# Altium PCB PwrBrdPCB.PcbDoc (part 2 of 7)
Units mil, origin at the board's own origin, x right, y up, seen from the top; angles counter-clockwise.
Board outline 8000 x 5500 mil, 4 copper layers (Top Layer, Internal 1, Internal 2, Bottom Layer), stack 61.834 mil thick; 682 components, 380 nets, 1899 pads, 766 vias.
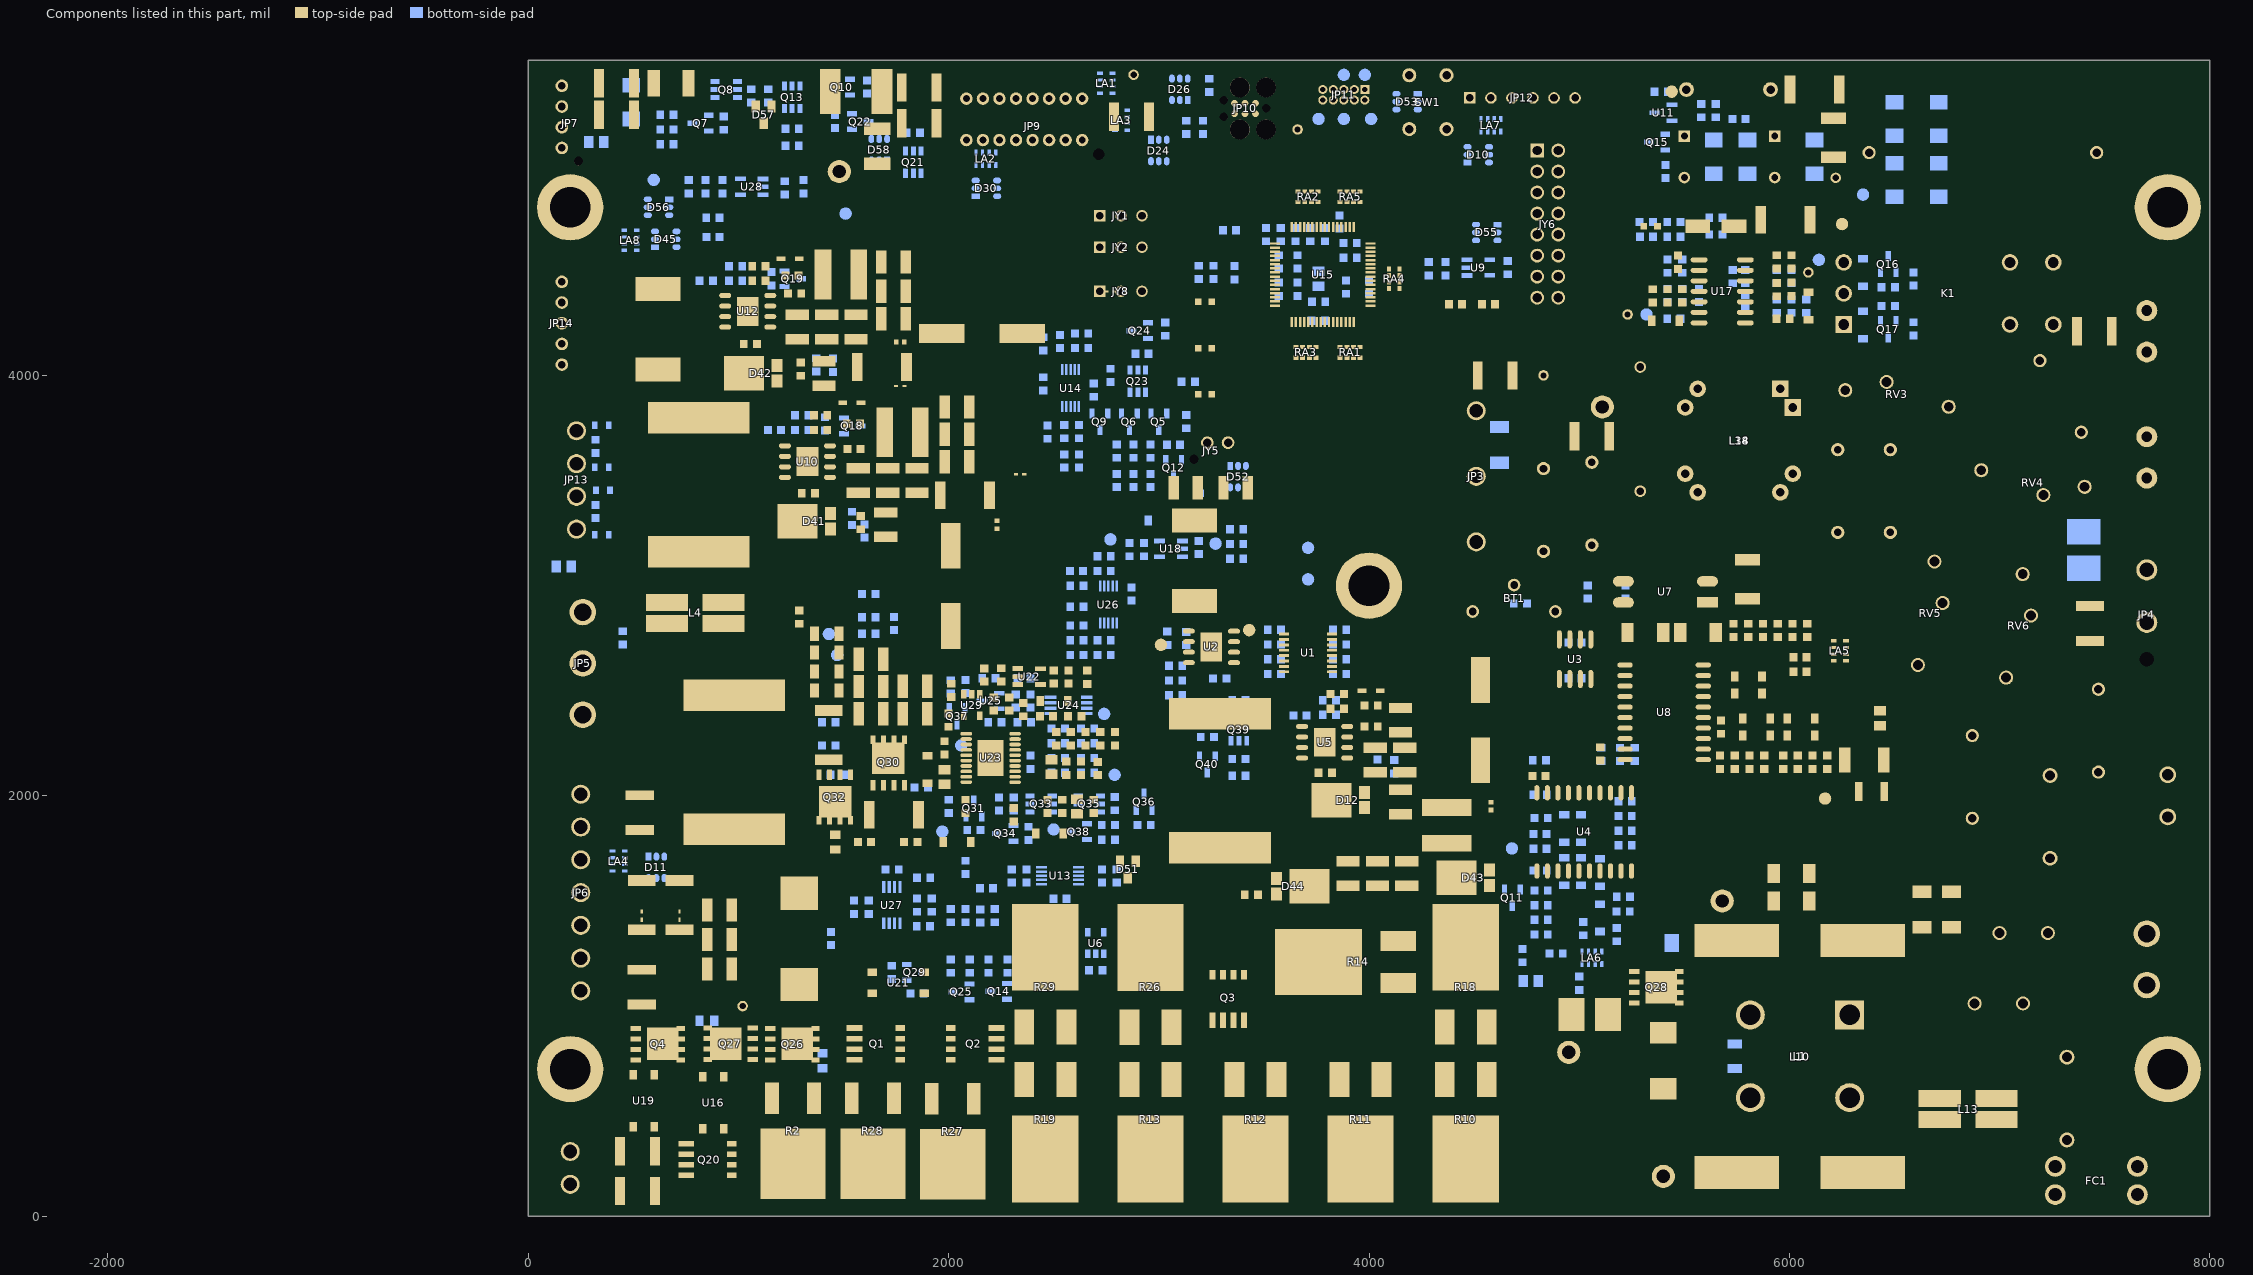
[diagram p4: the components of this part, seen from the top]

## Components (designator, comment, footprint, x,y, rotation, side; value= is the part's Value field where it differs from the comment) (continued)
R107 "1/10W 0603 0.1%" RESC1608X05AN[0603] 5580,5260 r270 bottom value=4220
R108 "1/10W 0603 0.1%" RESC1608X05AN[0603] 5650,4750 r0 bottom value=27400
R109 "1/10W 0603 1%" RESC1608X05AN[0603] 5320,4660 r180 bottom value=1000
R110 "1/10W 0603 1%" RESC1608X05AN[0603] 5450,4660 r180 bottom value=1000
R111 "1/10W 0603 1%" RESC1608X05AN[0603] 1550,3650 r180 top value=332000
R112 "1/10W 0603 1%" RESC1608X05AN[0603] 1600,3260 r90 bottom value=162000
R113 "1/10W 0603 1%" RESC1608X05AN[0603] 1171.5,3740 r0 bottom value=13000
R114 "1/10W 0603 1%" RESC1608X05AN[0603] 1547.13,3770 r0 top value=100000
R115 "1/10W 0603 1%" RESC1608X05AN[0603] 1540,3320 r90 bottom value=10000
R116 "1/10W 0603 1%" RESC1608X05AN[0603] 1391.5,3740 r180 top value=332000
R117 "1/10W 0603 1%" RESC1608X05AN[0603] 1391.5,3810 r180 top value=140000
R118 "3W 2512 1%" RESC6534X70[2512] 2077.13,3430 r180 top value=0.025
R119 "1/10W 0603 1%" RESC1608X05AN[0603] 1267.47,4390 r180 top value=332000
R120 "1/10W 0603 1%" RESC1608X05AN[0603] 1370,4050 r90 bottom value=52300
R121 "1/10W 0603 1%" RESC1608X05AN[0603] 847.13,4450 r0 bottom value=13000
R122 "1/10W 0603 1%" RESC1608X05AN[0603] 1157.13,4460 r90 bottom value=100000
R123 "1/10W 0603 1%" RESC1608X05AN[0603] 1255,4474.99 r0 top value=100000
R124 "1/10W 0603 1%" RESC1608X05AN[0603] 1450,4048.5 r90 bottom value=10000
R125 "1/10W 0603 1%" RESC1608X05AN[0603] 1097.13,4450 r180 top value=274000
R126 "1/10W 0603 1%" RESC1608X05AN[0603] 1097.13,4520 r180 top value=140000
R127 "3W 2512 1%" RESC6534X70[2512] 1682.87,4040 r180 top value=0.025
R128 "1/10W 0603 1%" RESC1608X05AN[0603] 2150,1428.5 r90 bottom value=1000
R129 "1/10W 0603 1%" RESC1608X05AN[0603] 2220,1430 r90 bottom value=1000
R130 "1/10W 0603 1%" RESC1608X05AN[0603] 2010,1430 r90 bottom value=1000
R131 "1/10W 0603 1%" RESC1608X05AN[0603] 2080,1430 r90 bottom value=1000
R132 "1/10W 0603 1%" RESC1608X05AN[0603] 2620,3592.87 r90 bottom value=1000
R133 "1/10W 0603 1%" RESC1608X05AN[0603] 2550,3592.87 r90 bottom value=1000
R134 "1/10W 0603 1%" RESC1608X05AN[0603] 2450,3960 r90 bottom value=1000
R135 "1/10W 0603 1%" RESC1608X05AN[0603] 2450,4150 r90 bottom value=1000
R136 "1/16W 0402" RESC1005X40[0402] 2230,3290 r270 top value=0.1
R137 "1/16W 0402" RESC1005X40[0402] 1770,4160 r0 top value=0.1
R138 "1/16W 0402" RESC1005X40[0402] 4580,1951.5 r90 top value=0.1
R139 "1/10W 0603 1%" RESC1608X05AN[0603] 930,5200 r270 bottom value=100000
R140 "3W 2512 1%" RESC6534X70[2512] 540,1480 r90 top value=0.01
R141 "1/10W 0603 1%" RESC1608X05AN[0603] 4411.5,4339.03 r0 top value=475000
R142 "1/10W 0603 1%" RESC1608X05AN[0603] 3380.95,2175.43 r0 bottom value=100000
R143 "1/10W 0603 1%" RESC1608X05AN[0603] 3380.95,2095.43 r0 bottom value=1000
R144 "1/10W 0603 1%" RESC1608X05AN[0603] 3232.25,2365.22 r180 bottom value=1000
R145 "1/10W 0603 1%" RESC1608X05AN[0603] 3380.95,2455.43 r0 bottom value=100000
R146 "1/10W 0603 1%" RESC1608X05AN[0603] 3230.95,2280 r180 bottom value=100000
R147 "1/10W 0603 1%" RESC1608X05AN[0603] 3360,4488.28 r90 bottom value=1000
R148 "1/10W 0603 1%" RESC1608X05AN[0603] 2465.8,2378.5 r180 top value=332000
R149 "1/10W 0603 1%" RESC1608X05AN[0603] 2355.3,2410 r90 top value=100000
R150 "1/10W 0603 1%" RESC1608X05AN[0603] 2214.78,2437.24 r90 top value=100000
R151 "1/10W 0603 1%" RESC1608X05AN[0603] 3336.5,4690.55 r180 bottom value=1000
R152 "1/10W 0603 1%" RESC1608X05AN[0603] 4568.5,4339.03 r180 top value=10000
R153 "1/10W 0603 1%" RESC1608X05AN[0603] 2190,1190 r90 bottom value=200
R154 "1/10W 0603 1%" RESC1608X05AN[0603] 2010,1190 r90 bottom value=200
R155 "1/10W 0603 1%" RESC1608X05AN[0603] 2280,1190 r270 bottom value=4750
R156 "1/10W 0603 1%" RESC1608X05AN[0603] 2100,1190 r270 bottom value=4750
R157 "1/10W 0603 1%" RESC1608X05AN[0603] 1850,1060 r180 bottom value=200
R158 "1/10W 0603 1%" RESC1608X05AN[0603] 1730,1160 r270 bottom value=4750
R159 "1/10W 0603 pulse" RESC1608X05AN[0603] 2310,1910 r90 top value=10
R160 "3W 2512 1%" RESC6534X70[2512] 720,1480 r90 top value=0.01
R161 "1/10W 0603 Jumper" RESC1608X05AN[0603] 2390,2160 r270 bottom value=0
R162 "1/10W 0603 pulse" RESC1608X05AN[0603] 2080,1950 r90 top value=10
R163 "1/10W 0603 1%" RESC1608X05AN[0603] 1870,2040 r180 bottom value=4.75
R164 "1/10W 0603 1%" RESC1608X05AN[0603] 2000,1950 r270 bottom value=100000
R165 "1/10W 0603 1%" RESC1608X05AN[0603] 1470,2100 r180 bottom value=4.75
R166 "1/10W 0603 1%" RESC1608X05AN[0603] 2120,1837.19 r180 bottom value=2740
R167 "1/10W 0603 1%" RESC1608X05AN[0603] 2470,1950 r270 top value=10000
R168 "1/10W 0603" RESC1608X05AN[0603] 2560,2131.5 r90 top value=38300
R169 "1W 2512 5%" RESC6534X70[2512] 1740,1910.39 r0 top value=100
R170 "1/10W 0603" RESC1608X05AN[0603] 1600,1780 r0 top value=301000
R171 "1/10W 0603 1%" RESC1608X05AN[0603] 1430,2240 r180 bottom value=47.5
R172 "3W 2512 1%" RESC6534X70[2512] 1430,2288.62 r90 top value=0.003
R173 "1/10W 0603 Jumper" RESC1608X05AN[0603] 4890,1250 r180 bottom value=0
R174 "1/10W 0603 1%" RESC1608X05AN[0603] 878.62,4750 r0 bottom value=4750
R175 "1/10W 0603 1%" RESC1608X05AN[0603] 1430,2350 r180 bottom value=47.5
R176 "1/10W 0603 0.1%" RESC1608X05AN[0603] 1620,2771.5 r0 bottom value=27400
R177 "1/10W 0603 1%" RESC1608X05AN[0603] 2310,1961.5 r270 bottom value=10000
R178 "1/10W 0603 0.1%" RESC1608X05AN[0603] 2511.49,2271.5 r270 top value=620
R179 "1/10W 0603 1%" RESC1608X05AN[0603] 2240,1961.5 r270 bottom value=4750
R180 "1/10W 0603 0.1%" RESC1608X05AN[0603] 2581.49,2271.5 r270 top value=3400
R181 "1/10W 0603 1%" RESC1608X05AN[0603] 2380,1821.5 r90 bottom value=100000
R182 "1/10W 0603 0.1%" RESC1608X05AN[0603] 2600,2378.51 r0 top value=1910
R183 "1/10W 0603 1%" RESC1608X05AN[0603] 2790,1962.99 r270 bottom value=1000
R184 "1/10W 0603 1%" RESC1608X05AN[0603] 2661.5,2110 r180 bottom value=100000
R185 "1/10W 0603 1%" RESC1608X05AN[0603] 2661.5,2250 r180 bottom value=100000
R186 "1/10W 0603 1%" RESC1608X05AN[0603] 2930,1861.5 r0 bottom value=100000
R187 "1/10W 0603 1%" RESC1608X05AN[0603] 2710,2130 r90 top value=1000
R188 "1/10W 0603 1%" RESC1608X05AN[0603] 2010,2518.5 r90 bottom value=1000
R189 "1/10W 0603 1%" RESC1608X05AN[0603] 2080,2520 r90 bottom value=10000
R190 "1/10W 0603 1%" RESC1608X05AN[0603] 2760,1861.5 r180 bottom value=1000
R191 "1/10W 0603 1%" RESC1608X05AN[0603] 2360,2350 r180 bottom value=2740
R192 "1/10W 0603 0.1%" RESC1608X05AN[0603] 2390,2451.5 r90 bottom value=4220
R193 "1/10W 0603 1%" RESC1608X05AN[0603] 2521.5,2110 r0 bottom value=100000
R194 "1/10W 0603 1%" RESC1608X05AN[0603] 2521.5,2250 r0 bottom value=100000
R195 "1/10W 0603 1%" RESC1608X05AN[0603] 2220,2350 r180 bottom value=100000
R196 "1/10W 0603 1%" RESC1608X05AN[0603] 2760,1791.5 r180 bottom value=100000
R197 "1/10W 0603 1%" RESC1608X05AN[0603] 2690,1950 r270 top value=1000
R198 "1/10W 0603 1%" RESC1608X05AN[0603] 2610,2670 r0 bottom value=1000
R199 "1/10W 0603 1%" RESC1608X05AN[0603] 2610,2810 r0 bottom value=1000
R200 "1/10W 0603 0.1%" RESC1608X05AN[0603] 1620,2850 r0 bottom value=27400
R201 "1/10W 0603 1%" RESC1608X05AN[0603] 2610,2900 r0 bottom value=1000
R202 "1/10W 0603 0.1%" RESC1608X05AN[0603] 2191.5,2560 r0 bottom value=620
R203 "1/10W 0603 1%" RESC1608X05AN[0603] 2608.5,3070 r0 bottom value=1000
R204 "1/10W 0603 0.1%" RESC1608X05AN[0603] 1850,1480 r270 bottom value=27400
R205 "1/10W 0603 0.1%" RESC1608X05AN[0603] 1920,1480 r90 bottom value=27400
R206 "1/10W 0603 0.1%" RESC1608X05AN[0603] 1550,1470 r270 bottom value=27400
R207 "1/10W 0603 0.1%" RESC1608X05AN[0603] 1620,1470 r90 bottom value=27400
R208 "1/10W 0603 1%" RESC1608X05AN[0603] 1881.24,1610 r0 bottom value=1000
R209 "1/10W 0603 0.1%" RESC1608X05AN[0603] 1440,1321.5 r90 bottom value=27400
R210 "1/10W 0603 1%" RESC1608X05AN[0603] 1880,1380 r0 bottom value=1000
R211 "1/10W 0603 0.1%" RESC1608X05AN[0603] 1731.5,1650 r0 bottom value=27400
R212 "1/10W 0603 1%" RESC1608X05AN[0603] 879.26,4658.54 r0 bottom value=4750
R213 "1/10W 0603 0.1%" RESC1608X05AN[0603] 1740,2820 r270 bottom value=27400
R214 "1/10W 0603 0.1%" RESC1608X05AN[0603] 1620,2960 r180 bottom value=27400
R215 "0.33W 1210 1%" RESC3225X70[1210]_HV 6390,2020 r180 top value=4700000
RA1 "22 5%" RESCAV80P320X160X70-8 3910,4110 r270 top value=22
RA2 "22 5%" RESCAV80P320X160X70-8 3710,4850 r270 top value=22
RA3 "22 5%" RESCAV80P320X160X70-8 3700,4110 r270 top value=22
RA4 "22 5%" RESCAV80P320X160X70-8 4120,4460 r0 top value=22
RA5 "22 5%" RESCAV80P320X160X70-8 3910,4850 r270 top value=22
RV1 "11VAC 14VDC MWV" LITTELFUSE_ULTRAMOV_20MM 6940,1180 r90 top value=11
RV2 "11VAC 14VDC MWV" LITTELFUSE_ULTRAMOV_20MM 7170,1180 r270 top value=11
RV3 "300V MWV" LITTELFUSE_ITMOV_20MM 6610,3910 r180 top value=300
RV4 "420V MWV" LITTELFUSE_ITMOV_20MM 7060,3490 r0 top value=420
RV5 "420V MWV" LITTELFUSE_ITMOV_20MM 6670,2770 r90 top value=420
RV6 "420V MWV" LITTELFUSE_ITMOV_20MM 7090,2710 r90 top value=420
SW1 "SPST-NO" TE_FSM2JH 4280,5300 r180 top locked
TP1 "TP SMD 1.5mm" TP_SMD_Ø1.5mm 4010,5220 r0 bottom locked
TP2 "TP SMD 1.5mm" TP_SMD_Ø1.5mm 3880,5220 r0 bottom locked
TP3 "TP TH  0.78mm" TP_TH078H127P 4830,4000 r90 top
TP4 "TP SMD 1.5mm" TP_SMD_Ø1.5mm 3980,5430 r0 bottom locked
TP5 "TP SMD 1.5mm" TP_SMD_Ø1.5mm 3880,5430 r0 bottom locked
TP6 "TP SMD 1.5mm" TP_SMD_Ø1.5mm 3760,5220 r270 bottom locked
TP7 "TP TH  0.78mm" TP_TH078H127P 5230,4290 r90 top locked
TP8 "TP TH  0.78mm" TP_TH078H127P 6090,4490 r270 top locked
TP9 "TP TH  0.78mm" TP_TH078H127P 6220,4940 r90 top locked
TP10 "TP SMD 1.5mm" TP_SMD_Ø1.5mm 3270,3200 r90 bottom locked
TP11 "TP BLK" KEYSTONE_5011 5680,1500 r90 top locked
TP12 "TP SMD 1.5mm" TP_SMD_Ø1.5mm 2770,3220 r0 bottom locked
TP13 "TP SMD 1.5mm" TP_SMD_Ø1.5mm 6250,4720 r90 top locked
TP14 "TP TH  0.78mm" TP_TH078H127P 3660,5170 r90 bottom
TP15 "TP TH  0.78mm" TP_TH078H127P 2880,5430 r90 bottom
TP16 "TP SMD 1.5mm" TP_SMD_Ø1.5mm 3430,2788.5 r180 top locked
TP17 "TP SMD 1.5mm" TP_SMD_Ø1.5mm 3010,2718.5 r180 top locked
TP18 "TP SMD 1.5mm" TP_SMD_Ø1.5mm 4680,1750 r90 bottom locked
TP19 "TP SMD 1.5mm" TP_SMD_Ø1.5mm 1510,4770 r90 bottom locked
TP20 "TP BLK" KEYSTONE_5011 1480,4970 r90 top locked
TP21 "TP BLK" KEYSTONE_5011 5110,3850 r0 top
TP22 "TP SMD 1.5mm" TP_SMD_Ø1.5mm 5440,5350 r90 top locked
TP23 "TP BLK" KEYSTONE_5011 5400,190 r0 top locked
TP24 "TP SMD 1.5mm" TP_SMD_Ø1.5mm 5320,4290 r90 bottom locked
TP25 "TP SMD 1.5mm" TP_SMD_Ø1.5mm 6140,4550 r270 bottom locked
TP26 "TP SMD 1.5mm" TP_SMD_Ø1.5mm 6350,4860 r90 bottom locked
TP27 "TP TH  0.78mm" TP_TH078H127P 1020,1000 r90 top locked
TP28 "TP SMD 1.5mm" TP_SMD_Ø1.5mm 3710,3180 r90 bottom locked
TP29 "TP SMD 1.5mm" TP_SMD_Ø1.5mm 3710,3030 r90 bottom locked
TP30 "TP BLK" KEYSTONE_5011 4950,780 r0 top locked
TP31 "TP SMD 1.5mm" TP_SMD_Ø1.5mm 2790,2100 r90 bottom locked
TP32 "TP SMD 1.5mm" TP_SMD_Ø1.5mm 1970,1830 r90 bottom locked
TP33 "TP SMD 1.5mm" TP_SMD_Ø1.5mm 6169.53,1987.24 r90 top locked
TP34 "TP SMD 1.5mm" TP_SMD_Ø1.5mm 2500,1840 r90 bottom locked
TP35 "TP SMD 1.5mm" TP_SMD_Ø1.5mm 597.32,4930 r90 bottom
TP36 "TP SMD 1.5mm" TP_SMD_Ø1.5mm 1430,2770 r90 bottom locked
TP37 "TP SMD 1.5mm" TP_SMD_Ø1.5mm 2060,2240 r90 bottom locked
TP38 "TP SMD 1.5mm" TP_SMD_Ø1.5mm 2740,2390 r90 bottom locked
TP39 "TP SMD 1.5mm" TP_SMD_Ø1.5mm 1470,2670 r90 bottom locked
U1 "Logic level translator" TSSOP16_ON 3710,2680 r180 top
U2 "AOZ3015" SOIC127P600X170_HS-9N 3250,2708.5 r0 top
U3 "RTC" SOIC127P600X170-8N 4980,2650 r90 top
U4 "ADE7903" SOIC127P1030X265-20N_smaller 5023.5,1828.62 r90 top
U5 "5A" SOIC127P600X170_HS-9N 3788.78,2255 r180 top
U6 "Address 0x4D" SOT-23-5 2700,1300 r180 bottom
U7 "LTV-814S" DIP4_SMD 5410,2970 r180 top
U8 "ADE7912" SOIC127P1030X265-20N 5404.09,2397.24 r180 top
U9 "16kbit I2C" SOT-23-5_MC 4520.28,4513.13 r0 bottom
U10 "5A" SOIC127P600X170_HS-9N 1328.62,3590 r180 top
U11 "TS3431" SOT_23_3 5400,5250 r180 bottom
U12 "5A" SOIC127P600X170_HS-9N 1044.41,4305 r180 top
U13 "ADS1115" TSSOP50P490X110-10N 2530,1620 r0 bottom
U14 "ADS1115" TSSOP50P490X110-10N 2580,3940 r90 bottom
U15 "48MHz 256k 32k" ATM-TQFP64 3780,4480 r90 top
U16 "PV Out" VISHAY_SOP-4 880,540 r270 top
U17 "LP2901DR" SOIC-14 5680,4400 r0 top
U18 "3.3V 200mA" TI-SOT-23-5_MC 3057.64,3175 r180 bottom
U19 "PV Out" VISHAY_SOP-4 550,550 r90 top
U21 "PV Out" VISHAY_SOP-4 1760,1110 r180 top
U22 "3.3V 200mA" TI-SOT-23-5_MC 2383,2567.41 r0 top
U23 "LM5117" TSOP65P640X110_HS-21N 2200,2180.39 r180 top
U24 "OPA2333" MSOP-8 2571.5,2430 r180 bottom
U25 "TS3431" SOT_23_3 2200,2451.5 r180 bottom
U26 "ADS1115" TSSOP50P490X110-10N 2760,2910 r90 bottom
U27 "OPA2333" MSOP-8 1730,1480 r90 bottom
U28 "3.3V 200mA" TI-SOT-23-5_MC 1063.99,4897.38 r180 bottom
U29 "LT6650" SOT-23-5 2110,2431.93 r180 top
Z1 "mounting hole" MOUNT_HOLE_5MM_8MM#1 7800,4800 r180 bottom locked
Z2 "mounting hole" MOUNT_HOLE_5MM_8MM#2 7800,700 r0 top
Z3 "NOBOM-00010" FIDUCIAL_1_3_KEEPOUT 4290,4240 r270 top
Z4 "NOBOM-00010" FIDUCIAL_1_3_KEEPOUT 360,920 r270 bottom
Z5 "mounting hole" MOUNT_HOLE_5MM_8MM#1 200,4800 r180 bottom locked
Z6 "mounting hole" MOUNT_HOLE_5MM_8MM#1 200,700 r180 bottom locked
Z7 "NOBOM-00010" FIDUCIAL_1_3_KEEPOUT 7800,5300 r180 bottom
Z8 "NOBOM-00010" FIDUCIAL_1_3_KEEPOUT 3450,4790 r0 top
Z9 "mounting hole" MOUNT_HOLE_5MM_8MM#3 4000,2950 r180 bottom
Z14 "NOBOM-00010" FIDUCIAL_1_3_KEEPOUT 7800,5300 r0 top
Z15 "NOBOM-00010" FIDUCIAL_1_3_KEEPOUT 360,920 r0 top

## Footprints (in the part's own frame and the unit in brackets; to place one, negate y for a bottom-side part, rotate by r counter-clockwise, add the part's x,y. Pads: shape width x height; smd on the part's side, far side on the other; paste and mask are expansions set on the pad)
AMP_1-1123723-2 [mm] "0.156\" (3.96mm) pitch header with latch"
  round 2.3 hole 1.65: 1(-1.981,0) 2(1.981,0)
  silkscreen extent -3.94,-4.83 3.94,3.7, body extent -3.93,-4.8 3.93,3.7, height 10.75
AMP_1-1123723-4 [mm] "0.156\" (3.96mm) pitch header with latch"
  round 2.3 hole 1.65: 1(-5.944,0) 2(-1.984,0) 3(1.976,0) 4(5.936,0)
  silkscreen extent -7.87,-4.83 7.87,3.3, body extent -7.89,-4.8 7.89,3.7, height 10.75
AMP_1-1123723-7 [mm] "0.156\" (3.96mm) pitch header with latch"
  round 2.3 hole 1.65: 1(-11.88,0) 2(-7.92,0) 3(-3.96,0) 4(0,0) 5(3.96,0) 6(7.92,0) 7(11.88,0)
  silkscreen extent -13.88,-4.8 13.92,3.3, body extent -13.83,-4.8 13.83,3.7, height 10.7
AMP_1-1123724-3 [mm] "0.156\" (3.96mm) pitch header with latch, alternating pins"
  round 2.3 hole 1.65: 1(-7.925,0) 3(0,0) 5(7.925,0)
  silkscreen extent -9.91,-4.83 9.91,3.3, body extent -9.87,-4.8 9.87,3.7, height 10.75
AMP_63849-1 [mil] "PCB-mount 0.250\" (or 0.187\") wide quick connect terminal, male vertical"
  round 80 hole 53.5: 1(-100,0) 1(100,0)
  silkscreen extent -170,-70 170,70, body extent -156,-61 156,61, height 409
ATM-TQFP64 [mm] "Thin QFP, 64-Leads, Body 10x10mm, Pitch 0.5mm, TQFP"
  rect 1.2x0.3 smd: 1(-5.75,3.75) 2(-5.75,3.25) 3(-5.75,2.75) 4(-5.75,2.25) 5(-5.75,1.75) 6(-5.75,1.25) 7(-5.75,0.75) 8(-5.75,0.25) 9(-5.75,-0.25) 10(-5.75,-0.75) 11(-5.75,-1.25) 12(-5.75,-1.75) 13(-5.75,-2.25) 14(-5.75,-2.75) 15(-5.75,-3.25) 16(-5.75,-3.75) 33(5.75,-3.75) 34(5.75,-3.25) 35(5.75,-2.75) 36(5.75,-2.25) 37(5.75,-1.75) 38(5.75,-1.25) 39(5.75,-0.75) 40(5.75,-0.25) 41(5.75,0.25) 42(5.75,0.75) 43(5.75,1.25) 44(5.75,1.75) 45(5.75,2.25) 46(5.75,2.75) 47(5.75,3.25) 48(5.75,3.75)
  rect 0.3x1.2 smd: 17(-3.75,-5.75) 18(-3.25,-5.75) 19(-2.75,-5.75) 20(-2.25,-5.75) 21(-1.75,-5.75) 22(-1.25,-5.75) 23(-0.75,-5.75) 24(-0.25,-5.75) 25(0.25,-5.75) 26(0.75,-5.75) 27(1.25,-5.75) 28(1.75,-5.75) 29(2.25,-5.75) 30(2.75,-5.75) 31(3.25,-5.75) 32(3.75,-5.75) 49(3.75,5.75) 50(3.25,5.75) 51(2.75,5.75) 52(2.25,5.75) 53(1.75,5.75) 54(1.25,5.75) 55(0.75,5.75) 56(0.25,5.75) 57(-0.25,5.75) 58(-0.75,5.75) 59(-1.25,5.75) 60(-1.75,5.75) 61(-2.25,5.75) 62(-2.75,5.75) 63(-3.25,5.75) 64(-3.75,5.75)
  silkscreen extent -5.99,-5.44 5.44,5.44, body extent -5,-5 5,5, height 1.6
BOURNS_PWR163 [mil] "power resistor, DPAK-like, but slightly different size."
  rect 150x65 smd: 1(-200,100) 2(-200,-100)
  rect 335x310 smd: 3(112.5,0)
  silkscreen extent -290,-170 290,170, body extent -90,-160 240,160, height 110
CAP_ALUM_SIZE-SVPF-B6 [mm]
  rect 3x1.6 smd: +(-2.2,0) -(2.2,0)
  silkscreen extent -3,-3 3,3, body extent -3,-2.65 3,2.65, height 5.9
CAP_RAD10P_DISC_10x5.5 [mm] "Radial disc 10mm lead spacing, 10mm dia, 5.5mm wide"
  round 1.6 hole 0.914: 1(-5,0) 2(5,0)
  silkscreen extent -5,-2.75 5,2.75, body extent -5.25,-2.75 5.25,2.75, height 12.5
CAP_RAD15P1805X11 [mm]
  round 1.4 hole 0.914: 1(-7.5,0) 2(7.5,0)
  silkscreen extent -9.5,-2.7 9.5,2.7, body extent -9.15,-2.6 9.15,2.6, height 11.2
CAP_RB5/10MMX20MM [mm] "Radial electrolytic 5mm pitch 10mm dia, 20mm high"
  rect 1.4x1.4 hole 0.838: +(2.5,0)
  round 1.4 hole 0.838: -(-2.5,0)
  silkscreen extent -5,-5 6.5,5, body extent -5.25,-5.22 5.25,5.28, height 22
CAPAE1300X1350D1370DD420L475N [mm]
  rect 5.51x2.32 smd: +(-4.85,0) -(4.85,0)
  silkscreen extent -8.38,-6.5 6.5,6.5, body extent -6.85,-6.5 6.85,6.5, height 13.5
CAPC1608X09N[0603] [mm]
  rect 0.95x1 smd: 1(-0.8,0) 2(0.8,0)
  silkscreen extent -1.53,-0.75 1.53,0.75, body extent -0.85,-0.45 0.85,0.45, height 0.9
CAPC2012X135 [mm]
  rect 1.16x1.47 smd: 1(-0.875,0) 2(0.875,0)
  silkscreen extent -0.3,-0.92 0.3,0.92, body extent -1,-0.63 1,0.63, height 1.35
CAPC3216X100 [mm]
  rect 1.06x1.71 smd: 1(-1.475,0) 2(1.475,0)
  silkscreen extent -0.95,-1.04 0.95,1.04, body extent -1.6,-0.8 1.6,0.8, height 1
CAPC3216X180 [mm]
  rect 1.06x1.71 smd: 1(-1.475,0) 2(1.475,0)
  silkscreen extent -0.95,-1.04 0.95,1.04, body extent -1.6,-0.8 1.6,0.8, height 1.8
CAPC3225X270 [mm]
  rect 1.26x2.81 smd: 1(-1.475,0) 2(1.475,0)
  silkscreen extent -0.85,-1.59 0.85,1.59, body extent -1.6,-1.25 1.6,1.25, height 2.7
CAPC4720X22N [mm] "Chip Capacitor, 2-Leads, Body 4.70x2.03mm, IPC Medium Density"
  rect 1.5x2.3 smd: 1(-2.15,0) 2(2.15,0)
  silkscreen extent -1,-1.05 1,1.05, body extent -2.54,-1.14 2.54,1.14, height 2.2
CNC_3220-10-0100-00 [mil] "shrouded 5x2 pin header with 0.050\" (1.27mm) spacing"
  rect 43x43 hole 25: 1(-25,100)
  round 43 hole 25: 2(25,100) 3(-25,50) 4(25,50) 5(-25,0) 6(25,0) 7(-25,-50) 8(25,-50) 9(-25,-100) 10(25,-100)
  silkscreen extent -115,-250 115,250, body extent -100,-249 100,249, height 213
DIP4_SMD [mil] "DIP package size, but SMD version"
  rect 100x50 smd: 1(-200,50)
  oval 100x50 smd: 2(-200,-50) 3(200,-50) 4(200,50)
  silkscreen extent -130,-91 130,92, body extent -130,-91 130,91, height 154
DO-204AL[DO-41] [mil]
  round 70 hole 40.5: A(200,0) K(-200,0)
  silkscreen extent -165,-55 165,55, body extent -216,-56 214,56, height 116
DO-214AB_SMC_BIDIR [mm]
  rect 2.6x3.2 smd: 1(-3.4,0) 2(3.4,0)
  silkscreen extent -3.57,-3.13 3.57,3.13, body extent -3.57,-3.13 3.57,3.13, height 2.65
DO-214AC [mil] "DIODE SCHOTTKY 5A 30V SMA"
  rect 70x85 smd: A(80,0) K(-80,0)
  silkscreen extent -146,-61 42,62, body extent -91,-57 91,57, height 96
FER1608X100[0603] [mm]
  rect 0.71x0.91 smd: 1(-0.85,0) 2(0.85,0)
  silkscreen extent -1.4,-0.6 1.4,0.6, body extent -0.8,-0.4 0.8,0.4, height 1
FERCAV80P320X160X70-4 [mm] "Ferrite Chip Array 0.8mm pitch x 4"
  rect 0.7x0.4 smd: 1(-0.75,1.2) 2(-0.75,0.4) 3(-0.75,-0.4) 4(-0.75,-1.2) 5(0.75,-1.2) 6(0.75,-0.4) 7(0.75,0.4) 8(0.75,1.2)
  silkscreen extent -1.2,-1.72 1.2,1.72, body extent -0.8,-1.58 0.8,1.6, height 0.9
FIDUCIAL_1_3_KEEPOUT [mil] "1mm dia fiducial with 3mm dia keepout"
  Top Layer circle w19.68: c0,0 r9.84
  Top Layer keep-out circle w10: c0,0 r56.1
FUSC7351X12N[2920] [mm] "Chip Fuse, 2-Leads, Body 7.36x5.12mm, IPC Medium Density"
  rect 2.5x5.45 smd: 1(-3.125,0) 2(3.125,0)
  silkscreen extent -4.5,-3 4.5,3, body extent -3.99,-2.72 3.99,2.72, height 1.25
Fuse-Bourns-MF-MSMF050-2 [mm] "PTC RESETTABLE .50A 15V 1812"
  rect 1.5x3.2 smd: 1(-2.1,0) 2(2.1,0)
  silkscreen extent -3.2,-1.9 3.2,1.9, body extent -2.4,-1.6 2.4,1.6, height 0.85
HARWIN_S8401-46 [mil] "Harwin S8401-46 vertical holder for CR2032"
  round 60 hole 36: +(-62.99,196.85) +(-62.99,-196.85) -(62.99,0)
  silkscreen extent -122,-453 130,453, body extent -116,-451 132,451, height 666
HDR_3PIN [mil] "3PIN SULLINS STRIP HEADER .100"
  rect 55x55 hole 36 paste-99999 mask+0: 1(-100,0)
  round 55 hole 36 paste-99999 mask+0: 2(0,0) 3(100,0)
  silkscreen extent -150,-50 148,50, body extent -150,-50 150,50, height 423
HDR_6PIN [mil] "6PIN BERG STRIP HEADER .100"
  rect 55x55 hole 36 paste-99999 mask+0: 1(-250,0)
  round 55 hole 36 paste-99999 mask+0: 2(-150,0) 3(-50,0) 4(50,0) 5(150,0) 6(250,0)
  silkscreen extent -300,-50 300,50, body extent -300,-50 300,50, height 423
INDC2012X110N[0805] [mm]
  rect 1.15x1.45 smd: 1(-0.9,0) 2(0.9,0)
  silkscreen extent -1.75,-1 1.75,1, body extent -1.02,-0.6 1.05,0.6, height 1.1
INDC4532X17N[1812] [mm] "Chip Inductor, 2-Leads, Body 4.50x3.20mm [1812], 1.7mm high, IPC Medium Density"
  rect 1.19x3.42 smd: 1(-2.105,0) 2(2.105,0)
  silkscreen extent -1.15,-1.61 1.15,1.61, body extent -2.35,-1.7 2.35,1.7, height 1.7
INDUCTOR-BOURNS_SRN6045 [mm] "SMT POWER INDUCTOR"
  rect 2x6 smd: 1(-2.15,0) 2(2.15,0)
  silkscreen extent -3.4,-3.3 3.4,3.3, body extent -3.01,-3.02 2.99,2.98, height 4.5
INDUCTOR-BOURNS_SRP1270 [mm] "SMT POWER INDUCTOR"
  rect 4x4.5 smd: 1(-5.5,0) 2(5.5,0)
  silkscreen extent -6.81,-6.81 6.81,6.81, body extent -6.25,-6.25 6.25,6.25, height 7
INDUCTOR-BOURNS_SRR1280 [mm] "SMT POWER INDUCTOR"
  rect 2.9x5.4 smd: 1(-4.85,0) 2(4.85,0)
  silkscreen extent -6.81,-6.81 6.81,6.81, body extent -6.27,-6.25 6.23,6.25, height 8
INDUCTOR_VISHAY_IHLP-6767 [mm] "SMT POWER INDUCTOR"
  rect 3.8x12.3 smd: 1(-8.1,0) 2(8.1,0)
  silkscreen extent -8.6,-8.6 8.6,8.6, body extent -8.56,-8.55 8.52,8.54, height 7
JST_B2B-XH-AM(LF)(SN) [mm] "JST XH type 2.5mm pitch 2-pin shrouded header with board guide"
  round 1 hole 1.11: 0(2.85,2)
  round 1.524 hole 1.029: 1(1.25,0) 2(-1.25,0)
  silkscreen extent -3.75,-2.4 3.75,3.4, body extent -3.7,-2.37 3.7,3.38, height 7
JST_B02P-VL [mm] "6.2mm pitch header with latch"
  round 3.2 hole 2.1: 1(-3.1,0) 2(3.1,0)
  silkscreen extent -6.7,-6.9 6.7,6.3, body extent -6.7,-6.9 6.7,6.3, height 16.5
JST_B03P-VL [mm] "6.2mm pitch header with latch"
  round 3.2 hole 2.1: 1(-6.2,0) 2(0,0) 3(6.2,0)
  silkscreen extent -9.8,-6.9 9.8,6.3, body extent -9.8,-6.9 9.8,6.3, height 16.5
JST_B4B-XH-AM(LF)(SN) [mil] "JST XH type 2.5mm pitch 4-pin shrouded header with a board guide"
  round 39.37 hole 43.7: 0(210.63,78.74)
  round 60 hole 36: 1(147.64,0) 2(49.21,0) 3(-49.21,0) 4(-147.64,0)
  silkscreen extent -246,-94 246,134, body extent -244,-93 244,133, height 276
JST_B5B-XH-A(LF)(SN) [mil]
  round 60 hole 36: 1(196.85,0) 2(98.43,0) 3(0,0) 4(-98.43,0) 5(-196.85,0)
  silkscreen extent -295,-94 295,134, body extent -293,-93 293,133, height 276
KEMET_PHE845VF6330MR06L2 [mm]
  round 1.6 hole 1.029: 1(-13.75,0) 2(13.75,0)
  silkscreen extent -15.8,-9.5 15.8,9.5, body extent -15.75,-9.5 15.75,9.5, height 29.05
KEMET_SCxx-yyGJ_17X17MM [mm] "Kemet SC-02-30GJ series and others"
  rect 2x2 hole 1.029: 1(-4,6.5)
  round 2 hole 1.029: 2(-4,-6.5) 3(4,-6.5) 4(4,6.5)
  silkscreen extent -8.8,-8.6 8.8,8.6, body extent -8.75,-8.5 8.75,8.5, height 20
KEYSTONE_3568 [mm] "Fuseholder, MINI ATC, MINI ATO"
  round 2.5 hole 1.6: 1(-4.96,-1.7) 1(-4.96,1.7) 2(4.96,-1.7) 2(4.96,1.7)
  silkscreen extent -8,-3.4 8,3.4, body extent -8,-3.35 8,3.38, height 7.46
KEYSTONE_5011 [mil] "TEST POINT PC MULTIPURPOSE BLK"
  round 110 / inner round 85 / far side round 110 hole 63: 1(0,0)
  silkscreen extent -66,-66 66,66, body extent -62,-62 63,63, height 320
LAIRD_CM3443Z171R-10 [mm] "Laird CM3443Z171R-10 CM choke"
  rect 2.03x5.08 smd: 1(-1.27,3.43) 2(-1.27,-3.43) 3(1.27,-3.43) 4(1.27,3.43)
  silkscreen extent -4.4,-6.2 4.4,6.2, body extent -4.3,-5.5 4.3,5.5, height 10.5
LEDC1608X06NGRN,0603, [mm] "LED GRN 0603"
  rect 0.8x0.8 smd: A(0.825,0) K(-0.825,0)
  silkscreen extent -1.99,-0.6 0.4,0.5, body extent -0.82,-0.4 0.79,0.4, height 0.55
LEDC1608X06NRED,0603, [mm] "LED RED 0603"
  rect 0.8x0.8 smd: A(0.825,0) K(-0.825,0)
  silkscreen extent -1.99,-0.6 0.4,0.5, body extent -0.82,-0.4 0.79,0.4, height 0.55
LEDC1608X06NYEL,0603, [mm] "LED YEL 0603"
  rect 0.8x0.8 smd: A(0.825,0) K(-0.825,0)
  silkscreen extent -1.99,-0.6 0.4,0.5, body extent -0.82,-0.4 0.79,0.4, height 0.55
LITTELFUSE_CG3x [mm] "for gas discharge tubes and other wide axial components"
  round 1.6 hole 1.029: 1(-5,0) 2(5,0)
  silkscreen extent -3.9,-4 3.9,4, body extent -5.4,-4 5.4,4, height 8
LITTELFUSE_ITMOV_20MM [mm] "MOV with thermal fusing and indicator lead"
  round 1.7 hole 1.2: 1(-3.75,1.5) 2(3.75,-1.5) 3(8.75,-0.5)
  silkscreen extent -11.25,-5 11.25,5, body extent -11.5,-3.5 11.5,3.5, height 27.5
LITTELFUSE_SL1411A [mm] "for gas discharge tubes and other wide axial components"
  round 1.8 hole 1.2: 1(-5,0) 2(5,0)
  silkscreen extent -3.9,-4 3.9,4, body extent -5.4,-4 5.4,4, height 8
LITTELFUSE_ULTRAMOV_20MM [mm] "MOV 20mm dia"
  round 1.7 hole 1.2: 1(-4.25,1.5) 2(4.25,-1.5)
  silkscreen extent -11.5,-2.6 11.5,2.6, body extent -11.4,-2.5 11.6,2.5, height 27.5
MOLEX_432550059 [mil] "Molex MLX 6.35mm series 2-pin with locator"
  round 20 hole 70 unplated: 0(-300,0)
  round 100 hole 70: 1(-125,0) 2(125,0)
  silkscreen extent -375,-200 375,150, body extent -356,-200 356,150, height 575
MOLEX_0559171610 [mm] "Molex MicroClasp dual row 2mm header 16 pins 8x2"
  round 1.5 hole 0.838: 1(-7,2.55) 2(-7,-2.45) 3(-5,2.55) 4(-5,-2.45) 5(-3,2.55) 6(-3,-2.45) 7(-1,2.55) 8(-1,-2.45) 9(1,2.55) 10(1,-2.45) 11(3,2.55) 12(3,-2.45) 13(5,2.55) 14(5,-2.45) 15(7,2.55) 16(7,-2.45)
  round 0.5 hole 1.359: ""(-9,4.25)
  silkscreen extent -9.7,-6.8 9.7,5, body extent -9.7,-6.6 9.7,4.9, height 9.75
MOUNT_HOLE_5MM_8MM#1 [mm] "hole sized for a 5mm screw"
  round 8 hole 4.902: 1(0,0)
MOUNT_HOLE_5MM_8MM#2 [mm] "hole sized for a 5mm screw"
  round 8 hole 4.902: 0(0,0)
MOUNT_HOLE_5MM_8MM#3 [mm] "hole sized for a 5mm screw"
  round 8 hole 4.902: 1(0,1.27)
MSOP-8 [mm] "SMT"
  rect 1.4x0.4 smd: 1(-2.2,0.975) 2(-2.2,0.325) 3(-2.2,-0.325) 4(-2.2,-0.975) 5(2.2,-0.975) 6(2.2,-0.325) 7(2.2,0.325) 8(2.2,0.975)
  silkscreen extent -2.37,-1.53 1.49,1.57, body extent -1.5,-1.53 1.5,1.47, height 1
NETTIE1608X05AN[0603] [mm]
  rect 0.95x1 smd: 1(-0.8,0) 2(0.8,0)
  Top Layer lines w0.5: 0.8,0 -0.8,0
  silkscreen extent -1.55,-0.75 1.55,0.75
NETTIE_0.254mm_NOPADS#1 [mm] "Net tie that is just a 0.254mm wide trace with no pads"
  rect 0.5x0.254 smd mask+0.102: 1(-0.5,0) 2(0.5,0)
  Top Layer lines w0.254: -0.5,0 0.5,0
  silkscreen extent -0.8,-0.2 0.8,0.2
NETTIE_0.254mm_NOPADS#2 [mm] "Net tie that is just a 0.254mm wide trace with no pads"
  rect 0.5x0.254 smd paste-0.254 mask+0.102: 1(-0.5,0) 2(0.5,0)
  Top Layer lines w0.254: 0.5,0 -0.5,0
  silkscreen extent -0.8,-0.2 0.8,0.2
PULSE_HCCI-80 [mm] "Pulse HCCI-80 CMC form"
  rect 4x10.2 smd: 1(-14,7.6) 2(-14,-7.6) 3(14,-7.6) 4(14,7.6)
  silkscreen extent -16.25,-13 16.25,13, body extent -15.5,-12.75 15.5,12.75, height 12.7
RESC1005X40[0402] [mm]
  rect 0.56x0.6 smd: 1(-0.47,0) 2(0.47,0)
  silkscreen extent -1.05,-0.6 1.05,0.6, body extent -0.5,-0.25 0.5,0.25, height 0.4
RESC1608X05AN[0603] [mm]
  rect 0.95x1 smd: 1(-0.8,0) 2(0.8,0)
  silkscreen extent -1.55,-0.75 1.55,0.75, body extent -0.85,-0.45 0.85,0.45, height 0.5
RESC2012X06N[0805] [mm] "Chip Resistor, 2-Leads, Body 2.00x1.20mm, IPC Medium Density"
  rect 1x1.25 smd: 1(-0.9,0) 2(0.9,0)
  silkscreen extent -1.6,-0.8 1.6,0.8, body extent -1.05,-0.63 1.05,0.63, height 0.6
RESC3225X70[1210]_HV [mm]
  rect 0.9x2.3 smd: 1(-1.55,0) 2(1.55,0)
  silkscreen extent -2.1,-1.3 2.1,1.3, body extent -1.6,-0.8 1.6,0.8, height 0.89
RESC5025X60,2010, [mil]
  rect 55x120 smd: 1(-92.52,0) 2(92.52,0)
  silkscreen extent -49,-49 49,49, body extent -101,-52 101,52, height 28
RESC6534X70[2512] [mm]
  rect 1.3x3.35 smd: 1(-2.975,0) 2(2.975,0)
  silkscreen extent -3.9,-1.9 3.9,1.9, body extent -3.25,-1.65 3.25,1.65, height 0.7
RESC6534X70[2512]_mOhm [mm] "Bourns recommended for 1-4 mOhm resistors"
  rect 3.1x4 smd: 1(-2.2,0) 2(2.2,0)
  silkscreen extent -3.9,-2.2 3.9,2.2, body extent -3.25,-1.65 3.25,1.65, height 0.7
RESCAV80P320X160X70-8 [mm] "Resistor or Capacitor Array 0.8mm pitch 0603 size x 4"
  rect 0.5x0.6 smd: 1(-0.65,1.2) 2(-0.65,0.4) 3(-0.65,-0.4) 4(-0.65,-1.2) 5(0.65,-1.2) 6(0.65,-0.4) 7(0.65,0.4) 8(0.65,1.2)
  silkscreen extent -1.12,-1.72 1.12,1.72, body extent -1.12,-1.72 1.12,1.72, height 0.55
SCHURTER_0751.0110 [mm] "single clip for 5x20 fuse"
  round 2.54 hole 1.3: 1(-2.5,0) 1(2.5,0)
  silkscreen extent -3.2,-2.9 3.81,2.9, body extent -3.1,-2.8 3.05,2.8, height 8.9
SOD-123 [mil]
  rect 36x48 smd: A(65.35,0) K(-65.35,0)
  silkscreen extent -111,-35 56,35, body extent -73,-31 73,31, height 53
SOD-323F [mm]
  rect 1.05x0.55 smd: A(1.1,0) K(-1.1,0)
  silkscreen extent -2.25,-0.68 0.9,0.68, body extent -1.25,-0.62 1.25,0.63, height 0.8
SOIC127P600X170-8N [mm] "SOIC, 8-Leads, Body 3.90x5mm, Pitch 1.27mm, IPC Medium Density"
  oval 2.2x0.6 smd: 1(-2.4,1.905) 2(-2.4,0.635) 3(-2.4,-0.635) 4(-2.4,-1.905) 5(2.4,-1.905) 6(2.4,-0.635) 7(2.4,0.635) 8(2.4,1.905)
  silkscreen extent -2.52,-2.5 0.9,2.88, body extent -3.02,-2.45 3.02,2.45, height 1.69
SOIC127P600X170_HS-9N [mm] "SOIC, 8-Leads, Body 4.90x3.90mm, Pitch 1.27mm, Thermal Pad 3.50x2.61mm, IPC Medium Density"
  oval 1.45x0.6 smd: 1(-2.725,1.905) 2(-2.725,0.635) 3(-2.725,-0.635) 4(-2.725,-1.905) 5(2.725,-1.905) 6(2.725,-0.635) 7(2.725,0.635) 8(2.725,1.905)
  rect 2.61x3.5 smd: 9(0,0)
  silkscreen extent -2.85,-2.5 1.6,2.88, body extent -2,-2.5 2,2.5, height 1.7
SOIC127P1030X265-20N [mm] "SOIC, 20-Leads, Body 15.30x7.50mm, Pitch 1.27mm, IPC Medium Density"
  oval 1.85x0.6 smd: 1(-4.725,5.715) 2(-4.725,4.445) 3(-4.725,3.175) 4(-4.725,1.905) 5(-4.725,0.635) 6(-4.725,-0.635) 7(-4.725,-1.905) 8(-4.725,-3.175) 9(-4.725,-4.445) 10(-4.725,-5.715) 11(4.725,-5.715) 12(4.725,-4.445) 13(4.725,-3.175) 14(4.725,-1.905) 15(4.725,-0.635) 16(4.725,0.635) 17(4.725,1.905) 18(4.725,3.175) 19(4.725,4.445) 20(4.725,5.715)
  silkscreen extent -4.85,-7.7 3.4,7.7, body extent -3.8,-7.7 3.8,7.7, height 2.65
SOIC127P1030X265-20N_smaller [mm] "SOIC, 20-Leads, Body 13.00x7.50mm, Pitch 1.27mm, IPC Medium Density"
  oval 1.85x0.6 smd: 1(-4.725,5.715) 2(-4.725,4.445) 3(-4.725,3.175) 4(-4.725,1.905) 5(-4.725,0.635) 6(-4.725,-0.635) 7(-4.725,-1.905) 8(-4.725,-3.175) 9(-4.725,-4.445) 10(-4.725,-5.715) 11(4.725,-5.715) 12(4.725,-4.445) 13(4.725,-3.175) 14(4.725,-1.905) 15(4.725,-0.635) 16(4.725,0.635) 17(4.725,1.905) 18(4.725,3.175) 19(4.725,4.445) 20(4.725,5.715)
  silkscreen extent -4.85,-6.5 3.4,6.69, body extent -3.8,-6.5 3.8,6.5, height 2.65
"SOIC-8 PPAK" [mm] "PowerPAK® SO-8"
  rect 3.81x3.91 smd: D(3.261,-1.868)
  rect 1.02x0.61 smd: D(5.464,-3.81) D(5.464,-2.54) D(5.464,-1.27) D(5.464,0)
  rect 1.27x0.61 smd: G(0,-3.81) S(0,-2.54) S(0,-1.27) S(0,0)
  silkscreen extent -0.14,-4.6 4.66,1.09, body extent -0.36,-4.36 5.68,0.54, height 1.69
SOIC-14 [mil] "SOIC 14pin 4mmX8.75mmX1.75mm 1.27mm pitch"
  oval 80x24 smd: 1(-110,150) 2(-110,100) 3(-110,50) 4(-110,0) 5(-110,-50) 6(-110,-100) 7(-110,-150) 8(110,-150) 9(110,-100) 10(110,-50) 11(110,0) 12(110,50) 13(110,100) 14(110,150)
  silkscreen extent -50,-175 50,175, body extent -79,-172 79,172, height 69
SOT23-3#1 [mil]
  rect 47.24x25 smd: 1(-39,37.4) 2(-39,-37.4) 3(39,0)
  silkscreen extent -28,-60 28,60, body extent -55,-57 55,57, height 50
SOT23-3#2 [mil]
  rect 25x47.24 smd: 1(-37.4,-39) 2(37.4,-39) 3(0,39)
  silkscreen extent -60,-28 60,28, body extent -57,-55 57,55, height 50
SOT23-3B [mm] "Aternate pin config"
  rect 1x1.4 smd: 1(0.95,1) 2(-0.95,1) 3(0,-1)
  silkscreen extent -1.52,-0.71 1.52,0.71, body extent -1.45,-1.4 1.45,1.4, height 1.28
SOT23-6 [mm]
  rect 0.99x0.69 smd: 1(-1.295,0.95)
  oval 0.99x0.69 smd: 2(-1.295,0) 3(-1.295,-0.95) 4(1.295,-0.95) 5(1.295,0) 6(1.295,0.95)
  silkscreen extent -1.61,-1.55 0.87,1.93, body extent -0.8,-1.5 0.8,1.5, height 1.25
SOT1205_LFPAK56D [mm] "LFPAK56D dual transistor package"
  rect 1.15x0.7 smd: 1(-3.275,1.905) 2(-3.275,0.635) 3(-3.275,-0.635) 4(-3.275,-1.905)
  rect 1.9x0.7 smd: 5(2.225,-1.905) 6(2.225,-0.635) 7(2.225,0.635) 8(2.225,1.905)
  Top Layer region: -2.1,-2.3 2,-2.3 2,-0.3 -2.1,-0.3
  Top Layer region: -2.1,0.3 2,0.3 2,2.3 -2.1,2.3
  silkscreen extent -3.4,-2.6 2.4,2.8, body extent -3.7,-2.6 3,2.6, height 1.1
SOT-23-5 [mil]
  rect 27x39 smd: 1(-37.5,-51) 2(0,-51) 3(37.5,-51) 4(37.5,51) 5(-37.5,51)
  silkscreen extent -60,-37 61,42, body extent -57,-55 57,55, height 50
SOT-23-5_MC [mil]
  rect 52x23.62 smd: 1(-53.99,37.4)
  rect 52x22 smd: 2(-53.99,0) 3(-53.99,-37.4) 4(53.99,-37.4) 5(53.99,37.4)
  silkscreen extent -62,-68 40,76, body extent -34,-60 34,60, height 57
SOT_23_3 [mm] "SOT23, 3-Leads, Body 2.90x2.45mm, Pitch 0.95mm, IPC Medium Density"
  rect 1.3x0.55 smd: 1(-1.05,0.95) 2(-1.05,-0.95) 3(1.05,0)
  silkscreen extent -1.08,-1.5 0.7,1.9, body extent -0.7,-1.5 0.7,1.5, height 1.1
SOT_23_6 [mm]
  rect 1.1x0.6 smd: 1(-1.35,0.95) 2(-1.35,0) 3(-1.35,-0.95) 4(1.35,-0.95) 5(1.35,0) 6(1.35,0.95)
  silkscreen extent -1.5,-1.59 1.19,1.7, body extent -0.87,-1.5 0.87,1.5, height 1.45
SULLINS_PRPC008DAAN-RC [mm] "PRPC008DAAN-RC"
  rect 1.67x1.67 / inner round 1.67 / far side rect 1.67x1.67 hole 1.11: 1(-8.89,-1.27)
  round 1.67 hole 1.11: 2(-8.89,1.27) 3(-6.35,-1.27) 4(-6.35,1.27) 5(-3.81,-1.27) 6(-3.81,1.27) 7(-1.27,-1.27) 8(-1.27,1.27) 9(1.27,-1.27) 10(1.27,1.27) 11(3.81,-1.27) 12(3.81,1.27) 13(6.35,-1.27) 14(6.35,1.27) 15(8.89,-1.27) 16(8.89,1.27)
  silkscreen extent -11.18,-3.1 11.18,3.09, body extent -10.16,-2.46 10.16,2.54, height 8.37
SULLINS_QPC02SXGN-RC [mil] "jumper (shunt)"
  body extent -98,-48 98,48, height 327
TAG-TC2030-LEGS [mm] "Tag-Connect TC2030 with legs footprint"
  round 2.375 hole 2.375 unplated mask+0: 0(-2.54,2.54) 0(-2.54,-2.54) 0(0.635,2.54) 0(0.635,-2.54)
  round 0.85 hole 1.029 unplated mask+0: 0(-2.54,0) 0(2.54,-1.016) 0(2.54,1.016)
  round 0.8 smd paste-0.4: 1(-1.27,-0.635) 2(-1.27,0.635) 3(0,-0.635) 4(0,0.635) 5(1.27,-0.635) 6(1.27,0.635)
  silkscreen extent -3.54,-1.8 3.5,1.8
TDK_B82732R [mm] "B82732R CMC"
  rect 2x2 hole 1.029: 1(-6.25,5)
  round 2 hole 1.029: 2(-6.25,-5) 3(6.25,-5) 4(6.25,5)
  silkscreen extent -12,-8.3 12,8.3, body extent -12,-8.25 12,8.25, height 23.5
TE_FSM2JH [mm] "TE Connnectivity FSM2JH momentary switch"
  round 1.7 hole 1.029: 1(2.25,3.25) 2(2.25,-3.25) 3(-2.25,3.25) 4(-2.25,-3.25)
  silkscreen extent -3,-3 3,3, body extent -2.99,-3.9 3,3.9, height 4.3
TE_RT1_2COIL_LATCHING [mm] "TE Connectivity/Schrack RT1/RT3 type latching SPST relay"
  round 2 hole 1.3: COM(-3.75,-7.85) COM(3.75,-7.85) NO(-3.75,-13.09) NO(3.75,-13.09) PLUS(0,12.25) SET(3.75,12.25)
  rect 2x2 hole 1.3: RESET(-3.75,12.25)
  silkscreen extent -6.35,-14.55 6.35,14.55, body extent -6.35,-14.55 6.35,14.55, height 16
TI-SOT-23-5_MC [mil]
  rect 52x23.62 smd: 1(-53.99,37.4)
  rect 52x22 smd: 2(-53.99,0) 3(-53.99,-37.4) 4(53.99,-37.4) 5(53.99,37.4)
  silkscreen extent -62,-68 40,77, body extent -34,-60 34,60, height 57
TO263_PWR_RES [mm] "D2-PAK, 3-Pads, Body 7.69x8.60mm (max), IPC Medium Density, like for Bourns PWR263S-35 series"
  rect 4.25x2.4 smd: 1(-6.375,2.54) 2(-6.375,-2.54)
  rect 10.5x8 smd: 3(3.25,0)
  Top Layer region: 4.5,-5.5 8.5,-5.5 8.5,5.5 4.5,5.5
  silkscreen extent -6.5,-5.25 -2.4,5.25, body extent -2.55,-5.25 6.63,5.25, height 4.88
TO-277_Z3N [mm]
  rect 1.57x1.29 smd: A1(-0.92,-2.88) A2(0.92,-2.88)
  rect 4.17x4.84 smd: K(0,1.1)
  silkscreen extent -2.27,-3.71 2.27,3.71, body extent -2,-3.4 2,3.4, height 1.35
TP_SMD_Ø1.5mm [mm]
  round 1.5 smd paste-5: 1(0,0)
  silkscreen extent -0.95,-0.95 0.95,0.95
TP_TH078H127P [mil] "30mil Trough Hole Test Point"
  round 50 hole 30 mask+0: 1(0,0)
TSOP65P640X110_HS-21N [mm] "TSOP, 20-Leads, Body 6.50x4.40mm, Pitch 0.65mm, Thermal Pad 4.35x3.15mm, IPC Medium Density"
  oval 1.4x0.45 smd: 1(-2.95,2.925) 2(-2.95,2.275) 3(-2.95,1.625) 4(-2.95,0.975) 5(-2.95,0.325) 6(-2.95,-0.325) 7(-2.95,-0.975) 8(-2.95,-1.625) 9(-2.95,-2.275) 10(-2.95,-2.925) 11(2.95,-2.925) 12(2.95,-2.275) 13(2.95,-1.625) 14(2.95,-0.975) 15(2.95,-0.325) 16(2.95,0.325) 17(2.95,0.975) 18(2.95,1.625) 19(2.95,2.275) 20(2.95,2.925)
  rect 3.15x4.35 smd: 21(0,0)
  silkscreen extent -3.08,-3.3 1.85,3.82, body extent -3.2,-3.3 3.2,3.3, height 1.1
TSSOP16_ON [mm] "4.4mm x 5mm x .65mm"
  rect 1.25x0.35 smd: 1(-2.9,2.275) 2(-2.9,1.625) 3(-2.9,0.975) 4(-2.9,0.325) 5(-2.9,-0.325) 6(-2.9,-0.975) 7(-2.9,-1.625) 8(-2.9,-2.275) 9(2.9,-2.275) 10(2.9,-1.625) 11(2.9,-0.975) 12(2.9,-0.325) 13(2.9,0.325) 14(2.9,0.975) 15(2.9,1.625) 16(2.9,2.275)
  silkscreen extent -4.23,-2.81 3.6,3.02, body extent -2.23,-2.49 2.17,2.51, height 1.2
TSSOP50P490X110-10N [mm] "TSSOP, 10-Leads, Body 3.00x3.00mm, Pitch 0.50mm, IPC Medium Density"
  rect 1.35x0.3 smd: 1(-2.225,1) 2(-2.225,0.5) 3(-2.225,0) 4(-2.225,-0.5) 5(-2.225,-1) 6(2.225,-1) 7(2.225,-0.5) 8(2.225,0) 9(2.225,0.5) 10(2.225,1)
  silkscreen extent -2.35,-1.55 1.15,1.82, body extent -1.55,-1.55 1.55,1.55, height 1.1
VISHAY_SOP-4 [mm] "Similar to DIP package size, but SMD, and slightly smaller"
  rect 1.15x0.9 smd: 1(-3.125,1.27) 2(-3.125,-1.27) 3(3.125,-1.27) 4(3.125,1.27)
  silkscreen extent -3.25,-2.5 2.5,2.5, body extent -2.3,-2.5 2.4,2.5, height 2.35
WURTH_S14100038 [mm] "Wurth S14100038 common-mode choke"
  rect 3.5x3.5 hole 2.5: 1(-5,6)
  round 3.5 hole 2.5: 2(-5,-6) 3(5,-6) 4(5,6)
  silkscreen extent -14,-9.75 14,9.75, body extent -14,-9.75 14,9.75, height 29

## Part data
BT1: library part CONN-00070, "HOLDER BATT COIN CR2032/20MM", manufacturer="Harwin Inc.", manufacturer_pn=S8401-46, Supplier Part Number 1=952-1743-1-ND
C1 C2 C70 C71: library part CAP-00055, "CAP CER 1000PF 250VAC X7R 1808", manufacturer="Johanson Dielectrics Inc.", manufacturer_pn=502R29W102KV3E-****-SC, Supplier Part Number 1=709-1269-1-ND, value_text=1n
C3 C4 C5 C8 C12 C17 C19 C21 C25 C28 C29 C44 C47 C53 C55 C57 C59 C61 C63 C67 C69 C72 C74 C75 C81 C83 C87 C89 C90 C91 C98 C99 C106 C111 C122 C135 C146 C152 C157 C163 C164 C166 C167 C168 C169 C170 C175 C176 C178 C179 C180 C182 C183 C188: library part CAP-00001, "0.10µF 50V Ceramic Capacitor X7R 0603 (1608 Metric) 0.063\" L x 0.031\" W (1.60mm x 0.80mm)", manufacturer="Murata Electronics North America", manufacturer_pn=GRM188R71H104KA93D, Supplier Part Number 1=490-1519-1-ND, value_text=0.1u
C6 C7 C11 C18 C20 C22 C34 C38 C43 C45 C46 C51 C52 C64 C65 C73 C76 C80 C82 C133 C134 C145 C184 C185 C187: library part CAP-00015, "4.7µF 25V Ceramic Capacitor X6S 0603 (1608 Metric) 0.063\" L x 0.031\" W (1.60mm x 0.80mm)", manufacturer="Murata Electronics North America", manufacturer_pn=GRM188C81E475KE11D, Supplier Part Number 1=490-7199-1-ND, value_text=4.7u
C9 C10 C15 C16 C36 C37 C50 C54 C56 C58 C60 C62 C77 C78 C79 C86 C88: library part CAP-00000, "0.033µF 50V Ceramic Capacitor X7R 0603 (1608 Metric) 0.063\" L x 0.031\" W (1.60mm x 0.80mm)", manufacturer="Murata Electronics North America", manufacturer_pn=GRM188R71H333KA61D, Supplier Part Number 1=490-3286-1-ND, value_text=33n
C13 C107 C108 C109 C110 C112 C113 C114 C115 C144 C162 C165 C171 C172 C173 C174 C186: library part CAP-00027, "10000pF 50V Ceramic Capacitor C0G, NP0 0603 (1608 Metric) 0.063\" L x 0.031\" W (1.60mm x 0.80mm)", manufacturer="Murata Electronics North America", manufacturer_pn=GRM1885C1H103JA01D, Supplier Part Number 1=490-9666-1-ND, value_text=10n
C14 C155: library part CAP-00043, "33pF 50V Ceramic Capacitor C0G, NP0 0603 (1608 Metric) 0.063\" L x 0.031\" W (1.60mm x 0.80mm)", manufacturer="Murata Electronics North America", manufacturer_pn=GRM1885C1H330JA01D, Supplier Part Number 1=490-1415-1-ND, value_text=33p
C23 C48 C92 C100 C181: library part CAP-00050, "47µF ±20% 16V Ceramic Capacitor X5R 1210 (3225 Metric)", manufacturer="Murata Electronics North America", manufacturer_pn=GRM32ER61C476ME15L, Supplier Part Number 1=490-3888-1-ND, value_text=47u
C24 C94 C95 C102 C103 C117 C119 C121 C123 C124 C125 C126 C127 C128 C129 C130 C131 C132 C136 C137 C138 C139 C140 C141 C142 C143: library part CAP-00075, "4.7µF ±10% 100V Ceramic Capacitor X5R 1210 (3225 Metric)", manufacturer="Taiyo Yuden", manufacturer_pn=HMK325BJ475KM-PE, Supplier Part Number 1=587-5034-1-ND, value_text=4.7u
C26 C96 C104: library part CAP-00035, "0.022µF 50V Ceramic Capacitor X7R 0603 (1608 Metric) 0.063\" L x 0.031\" W (1.60mm x 0.80mm)", manufacturer="Murata Electronics North America", manufacturer_pn=GRM188R71H223KA01D, Supplier Part Number 1=490-1517-1-ND, value_text=22n
C27 C97 C105 C161: library part CAP-00051, "16pF ±5% 50V Ceramic Capacitor C0G, NP0 0603 (1608 Metric)", manufacturer="Murata Electronics North America", manufacturer_pn=GRM1885C1H160JA01D, Supplier Part Number 1=490-1408-1-ND, value_text=16p
C30 C39 C41 C42: library part CAP-00040, "2200pF 400VAC Ceramic Capacitor Y5V (F) Radial, Disc 0.354\" Dia (9.00mm)", manufacturer=Kemet, manufacturer_pn=C921U222MVVDBA7317, Supplier Part Number 1=399-9487-1-ND, value_text=2.2n
C31: library part CAP-00039, "0.33µF Film Capacitor 760V 1500V (1.5kV) Polypropylene (PP), Metallized Radial 1.240\" L x 0.748\" W (31.50mm x 19.00mm)", manufacturer=Kemet, manufacturer_pn=PHE845VF6330MR06L2, Supplier Part Number 1=399-10102-ND, value_text=0.33u
C32 C33: library part CAP-00032, "470µF 35V Aluminum Capacitors Radial, Can 2000 Hrs @ 105°C", manufacturer=Kemet, manufacturer_pn=ESH477M035AH3AA, Supplier Part Number 1=399-6592-ND, value_text=470u
C35: library part CAP-00073, "22µF 35V Aluminum Electrolytic Capacitors Radial, Can - SMD 1 Ohm @ 100kHz 2000 Hrs @ 105°C", manufacturer=Kemet, manufacturer_pn=EEV226M035A9DAA, Supplier Part Number 1=399-6706-1-ND, value_text=22u
C40 C84 C85: library part CAP-00066, "CAP CER 220PF 250VAC X7R 1808", manufacturer="Murata Electronics North America", manufacturer_pn=GA342DR7GF221KW02L, Supplier Part Number 1=490-3473-1-ND, value_text=220p
C49 C66 C68 C93 C101 C153 C159 C160 C177: library part CAP-00053, "1000pF ±5% 50V Ceramic Capacitor C0G, NP0 0603 (1608 Metric)", manufacturer="Murata Electronics North America", manufacturer_pn=GRM1885C1H102JA01D, Supplier Part Number 1=490-1451-1-ND, value_text=1n
C116 C118 C120: library part CAP-00072, "68µF 80V Aluminum Electrolytic Capacitors Radial, Can - SMD 5000 Hrs @ 105°C", manufacturer="Panasonic Electronic Components", manufacturer_pn=EEV-FK1K680Q, Supplier Part Number 1=PCE3528CT-ND, value_text=68u
C147 C154 C156: library part CAP-00076, "0.47µF ±10% 100V Ceramic Capacitor X7S 0805 (2012 Metric)", manufacturer="Taiyo Yuden", manufacturer_pn=HMK212C7474KGHTE, Supplier Part Number 1=587-5014-1-ND, value_text=0.47u
C148 C149 C150 C151: library part CAP-00074, "10µF ±20% 50V Ceramic Capacitor X5R 1206 (3216 Metric)", manufacturer="TDK Corporation", manufacturer_pn=C3216X5R1H106M160AB, Supplier Part Number 1=445-5999-1-ND, value_text=10u
C158: library part CAP-00078, "100pF ±5% 50V Ceramic Capacitor C0G, NP0 0603 (1608 Metric)", manufacturer="Murata Electronics North America", manufacturer_pn=GRM1885C1H101JA01D, Supplier Part Number 1=490-1427-1-ND, value_text=100p
CX1: library part CAP-00054, "CAP CER 0.022UF 100V X7R 1206", manufacturer=Kemet, manufacturer_pn=C1206C223J1RACTU, Supplier Part Number 1=399-9329-1-ND, value_text=22n
CX2: library part CAP-00037, "0.022µF Film Capacitor 275V 560V Polypropylene (PP), Metallized Radial 0.709\" L x 0.197\" W (18.00mm x 5.00mm)", manufacturer=Kemet, manufacturer_pn=R46KI22200001K, Supplier Part Number 1=399-9645-ND, value_text=22n
D1 D18: library part LED-00005, "Red 633nm LED Indication - Discrete 2V 0603 (1608 Metric) 28mcd min, 104mcd typ., diffused", manufacturer="OSRAM Opto Semiconductors Inc.", manufacturer_pn="LS Q976-NR-1", Supplier Part Number 1=475-2512-1-ND
D2 D9 D46 D54: library part DIO-00007, "Diode Schottky 40V 500mA Surface Mount SOD-123", manufacturer="Fairchild Semiconductor", manufacturer_pn=MBR0540, Supplier Part Number 1=MBR0540CT-ND
D3: library part LED-00006, "Yellow 591nm LED Indication - Discrete 2.1V 0603 (1608 Metric) 104mcd clear", manufacturer="Lite-On Inc.", manufacturer_pn=LTST-C191KSKT, Supplier Part Number 1=160-1448-1-ND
